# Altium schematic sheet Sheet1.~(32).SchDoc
size A; SheetNumber: 1; SheetTotal: 1
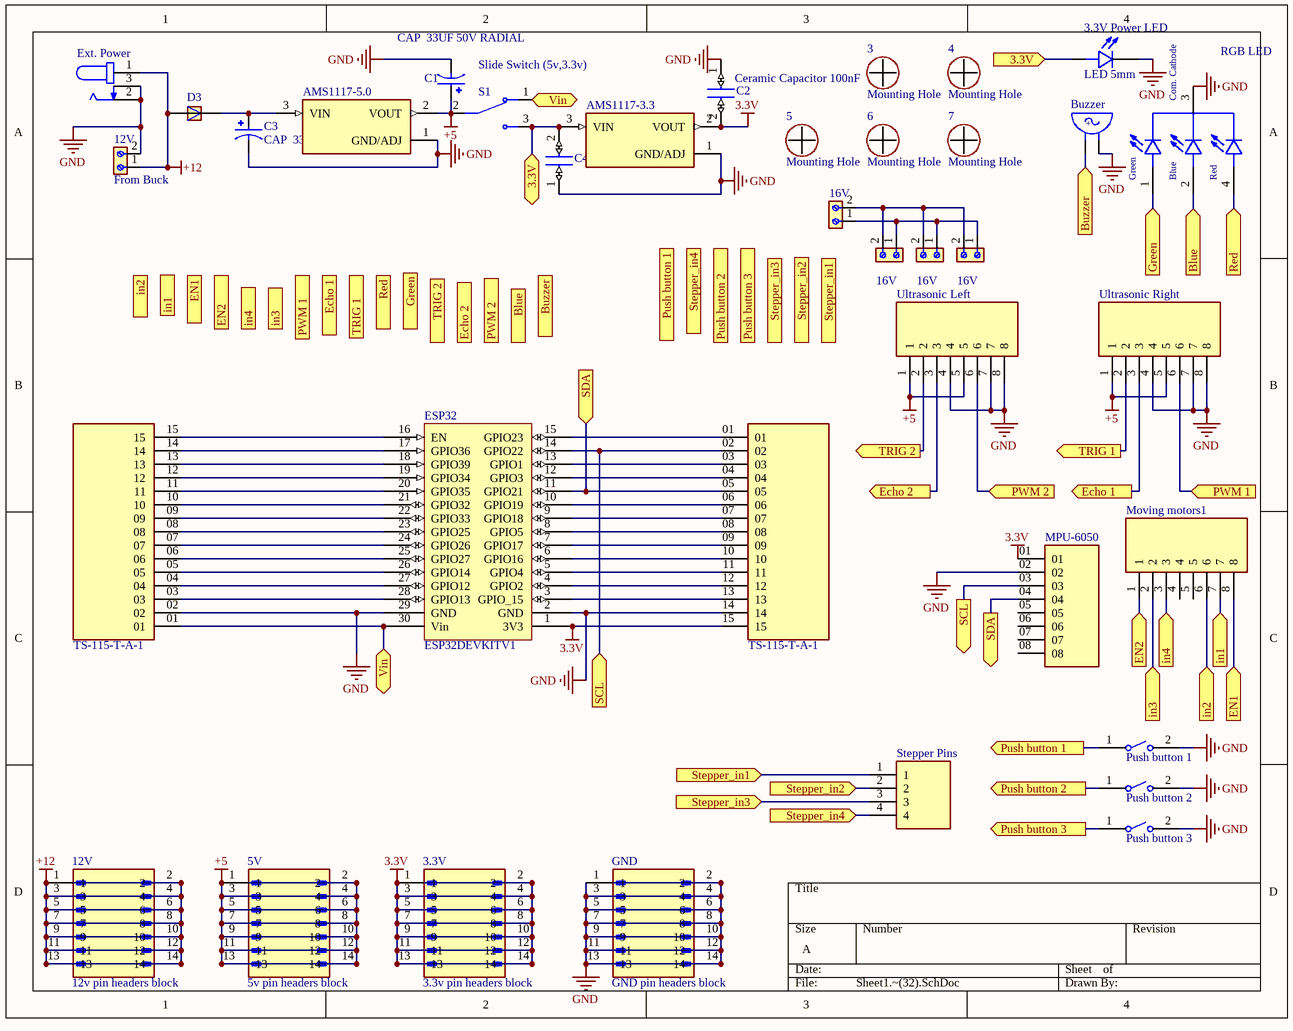
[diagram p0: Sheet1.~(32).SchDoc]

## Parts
(Parts that share a designator on the sheet are numbered #1, #2 ... from top to bottom, then left to right.)
3  Mounting Hole  [PCBComponent_1]
3.3V  3.3v pin headers block  [AMPHENOL_52601-S14-4LF]
3.3V_Power_LED  LED 5mm  [LED 5mm]
4  Mounting Hole  [PCBComponent_1]
5  Mounting Hole  [PCBComponent_1]
5V  5v pin headers block  [AMPHENOL_52601-S14-4LF]
6  Mounting Hole  [PCBComponent_1]
7  Mounting Hole  [PCBComponent_1]
12V#1  From Buck  [691213510002]
12V#2  12v pin headers block  [AMPHENOL_52601-S14-4LF]
16V#1  From Buck  [691213510002]  (value not drawn)
16V#2  From Buck  [691213510002]  (value not drawn)
16V#3  From Buck  [691213510002]  (value not drawn)
16V#4  From Buck  [691213510002]  (value not drawn)
AMS1117-3.3  AMS1117-3.3  [SOT229P700X180-4N]  (value not drawn)
AMS1117-5.0  AMS1117-5.0  [SOT229P700X180-4N]  (value not drawn)
Buzzer  Buzzer  [Buzzer 5V]  (value not drawn)
C1  CAP  33UF 50V RADIAL  [CAP  33UF 50V RADIAL]
C2  Ceramic Capacitor 100nF  [C320C]
C3  CAP  33UF 50V RADIAL  [CAP  33UF 50V RADIAL]
C4  Ceramic Capacitor 100nF  [C320C]  (value not drawn)
D3  RL207  [DIOAD1300W80L670D310]  (value not drawn)
ESP32  ESP32DEVKITV1  [ESP32DEVKITV1]
Ext._Power  DC Power Jack Female Socket  [DC Power Jack Female Socket]  (value not drawn)
GND  GND pin headers block  [AMPHENOL_52601-S14-4LF]
J5  TS-115-T-A-1  [SAMTEC_TS-115-T-A-1]
J6  TS-115-T-A-1  [SAMTEC_TS-115-T-A-1]
Moving_motors1  Pin header female block 8 pin  [Pin header female block 8 pin]  (value not drawn)
MPU-6050  MPU-6050  [MPU-6050]  (value not drawn)
Push_button_1  FSM8JRT  [TE_FSM8JRT]  (value not drawn)
Push_button_2  FSM8JRT  [TE_FSM8JRT]  (value not drawn)
Push_button_3  FSM8JRT  [TE_FSM8JRT]  (value not drawn)
RGB_LED  common cathode  [LED RGB 5mm]  (value not drawn)
S1  Slide Switch (5v,3.3v)  [Slide switch]
Stepper_Pins  Pin hreader 4 pins  [Pin hreader 4 pins]  (value not drawn)
Ultrasonic_Left  Pin header female block 8 pin  [Pin header female block 8 pin]  (value not drawn)
Ultrasonic_Right  Pin header female block 8 pin  [Pin header female block 8 pin]  (value not drawn)

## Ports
3.3V (bidir, see Sheet1[4A]), 3.3V (in, see Sheet1[2A]), Blue (in, see Sheet1[2B]), Blue (out, see Sheet1[4B]), Buzzer (in, see Sheet1[2B]), Buzzer (out, see Sheet1[4A]), Echo 1 (in, see Sheet1[4B]), Echo 1 (out, see Sheet1[2B]), Echo 2 (in, see Sheet1[3B]), Echo 2 (out, see Sheet1[2B]), EN1 (in, see Sheet1[1B]), EN1 (out, see Sheet1[4C]), EN2 (in, see Sheet1[1B]), EN2 (out, see Sheet1[4C]), Green (in, see Sheet1[2B]), Green (out, see Sheet1[4B]), in1 (in, see Sheet1[1B]), in1 (out, see Sheet1[4C]), in2 (in, see Sheet1[1B]), in2 (out, see Sheet1[4C]), in3 (in, see Sheet1[1B]), in3 (out, see Sheet1[4C]), in4 (in, see Sheet1[1B]), in4 (out, see Sheet1[4C]), Push button 1 (in, see Sheet1[4C]), Push button 1 (out, see Sheet1[3B]), Push button 2 (in, see Sheet1[4D]), Push button 2 (out, see Sheet1[3B]), Push button 3 (in, see Sheet1[4D]), Push button 3 (out, see Sheet1[3B]), PWM 1 (in, see Sheet1[1B]), PWM 1 (out, see Sheet1[4B]), PWM 2 (in, see Sheet1[2B]), PWM 2 (out, see Sheet1[4B]), Red (in, see Sheet1[2B]), Red (out, see Sheet1[4B]), SCL (in, see Sheet1[3C]), SCL (out, see Sheet1[2C]), SDA (in, see Sheet1[4C]), SDA (out, see Sheet1[2B]), Stepper_in1 (in, see Sheet1[3B]), Stepper_in1 (in, see Sheet1[3D]), Stepper_in2 (in, see Sheet1[3B]), Stepper_in2 (in, see Sheet1[3D]), Stepper_in3 (in, see Sheet1[3B]), Stepper_in3 (in, see Sheet1[3D]), Stepper_in4 (in, see Sheet1[3B]), Stepper_in4 (out, see Sheet1[3D]), TRIG 1 (in, see Sheet1[4B]), TRIG 1 (out, see Sheet1[2B]), TRIG 2 (out, see Sheet1[2B]), TRIG 2 (out, see Sheet1[3B]), Vin (bidir, see Sheet1[2A]), Vin (bidir, see Sheet1[2C])

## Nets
3.3V: 3.3V.1 3.3V.2 3.3V.3 3.3V.4 3.3V.5 3.3V.6 3.3V.7 3.3V.8 3.3V.9 3.3V.10 3.3V.11 3.3V.12 3.3V.13 3.3V.14 AMS1117-3.3.2(VOUT) C2.2 ESP32.1(3V3) J5.15 MPU-6050.01
+5: 5V.1 5V.2 5V.3 5V.4 5V.5 5V.6 5V.7 5V.8 5V.9 5V.10 5V.11 5V.12 5V.13 5V.14 AMS1117-5.0.2(VOUT) C1.P S1.2 Ultrasonic_Left.1 Ultrasonic_Left.5 Ultrasonic_Right.1 Ultrasonic_Right.5
+12: 12V#1.1 12V#2.1 12V#2.2 12V#2.3 12V#2.4 12V#2.5 12V#2.6 12V#2.7 12V#2.8 12V#2.9 12V#2.10 12V#2.11 12V#2.12 12V#2.13 12V#2.14 D3.A Ext._Power.1
GND: 3.3V_Power_LED.C 12V#1.2 AMS1117-3.3.1(GND/ADJ) AMS1117-5.0.1(GND/ADJ) Buzzer.NEG C1.N C2.1 C3.N C4.1 ESP32.2(GND) ESP32.29(GND) Ext._Power.2 Ext._Power.3 GND.1 GND.2 GND.3 GND.4 GND.5 GND.6 GND.7 GND.8 GND.9 GND.10 GND.11 GND.12 GND.13 GND.14 J5.14 J6.02 MPU-6050.02 Push_button_1.2 Push_button_2.2 Push_button_3.2 RGB_LED.3(Com._Cathode) Ultrasonic_Left.4 Ultrasonic_Left.7 Ultrasonic_Left.8 Ultrasonic_Right.4 Ultrasonic_Right.7 Ultrasonic_Right.8
3.3V: 3.3V_Power_LED.A AMS1117-3.3.3(VIN) C4.2 S1.3 ; port 3.3V  [a separate net that carries the same name]
Blue: RGB_LED.2(BLUE) ; port Blue
Buzzer: Buzzer.POS ; port Buzzer
Echo 1: Ultrasonic_Right.3 ; port Echo 1
Echo 2: Ultrasonic_Left.3 ; port Echo 2
EN1: Moving_motors1.8 ; port EN1
EN2: Moving_motors1.1 ; port EN2
Green: RGB_LED.1(Green) ; port Green
in1: Moving_motors1.7 ; port in1
in2: Moving_motors1.6 ; port in2
in3: Moving_motors1.2 ; port in3
in4: Moving_motors1.3 ; port in4
Push button 1: Push_button_1.1 ; port Push button 1
Push button 2: Push_button_2.1 ; port Push button 2
Push button 3: Push_button_3.1 ; port Push button 3
PWM 1: Ultrasonic_Right.6 ; port PWM 1
PWM 2: Ultrasonic_Left.6 ; port PWM 2
Red: RGB_LED.4(Red) ; port Red
SCL: ESP32.14(GPIO22) J5.02 MPU-6050.03 ; port SCL
SDA: ESP32.11(GPIO21) J5.05 MPU-6050.04 ; port SDA
Stepper_in1: Stepper_Pins.1 ; port Stepper_in1
Stepper_in2: Stepper_Pins.2 ; port Stepper_in2
Stepper_in3: Stepper_Pins.3 ; port Stepper_in3
Stepper_in4: Stepper_Pins.4 ; port Stepper_in4
TRIG 1: Ultrasonic_Right.2 ; port TRIG 1
TRIG 2: Ultrasonic_Left.2 ; port TRIG 2
Vin: ESP32.30(Vin) J6.01 S1.1 ; port Vin
Net16V#1_1: 16V#1.1 16V#2.1 16V#3.1 16V#4.1
Net16V#1_2: 16V#1.2 16V#2.2 16V#3.2 16V#4.2
NetAMS1117-5.0_3: AMS1117-5.0.3(VIN) C3.P D3.C
NetESP32_3: ESP32.3(GPIO_15) J5.13
NetESP32_4: ESP32.4(GPIO2) J5.12
NetESP32_5: ESP32.5(GPIO4) J5.11
NetESP32_6: ESP32.6(GPIO16) J5.10
NetESP32_7: ESP32.7(GPIO17) J5.09
NetESP32_8: ESP32.8(GPIO5) J5.08
NetESP32_9: ESP32.9(GPIO18) J5.07
NetESP32_10: ESP32.10(GPIO19) J5.06
NetESP32_12: ESP32.12(GPIO3) J5.04
NetESP32_13: ESP32.13(GPIO1) J5.03
NetESP32_15: ESP32.15(GPIO23) J5.01
NetESP32_16: ESP32.16(EN) J6.15
NetESP32_17: ESP32.17(GPIO36) J6.14
NetESP32_18: ESP32.18(GPIO39) J6.13
NetESP32_19: ESP32.19(GPIO34) J6.12
NetESP32_20: ESP32.20(GPIO35) J6.11
NetESP32_21: ESP32.21(GPIO32) J6.10
NetESP32_22: ESP32.22(GPIO33) J6.09
NetESP32_23: ESP32.23(GPIO25) J6.08
NetESP32_24: ESP32.24(GPIO26) J6.07
NetESP32_25: ESP32.25(GPIO27) J6.06
NetESP32_26: ESP32.26(GPIO14) J6.05
NetESP32_27: ESP32.27(GPIO12) J6.04
NetESP32_28: ESP32.28(GPIO13) J6.03

Not connected (* = marked no-connect by the designer): Moving_motors1 4 5; MPU-6050 05 06 07 08

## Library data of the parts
3.3V 5V 12V#2 GND = 52601-S14-4LF: MF: {'manufacturer': u'Amphenol ICC (FCI)'}
3.3V_Power_LED = LED 5mm: Red 623nm LED Indication - Discrete 1.9V Radial; MF: {'manufacturer': u'Wurth Elektronik'}; MP: 151054RS03000
12V#1 16V#1-16V#4 = Terminal Block: 2 Position Wire to Board Terminal Block Horizontal with Board 0.200 (5.08mm) Through Hole; MF: Wurth Electronics
AMS1117-3.3 = AMS1117-3.3: MF: {'manufacturer': u'Advanced Monolithic Systems'}
AMS1117-5.0 = AMS1117-5.0: MF: {'manufacturer': u'Advanced Monolithic Systems'}
Buzzer = Buzzer 5V: BUZZER 2.3KHZ 4-6VDC; MF: {'manufacturer': u'Soberton Inc.'}; MP: WST-1205S
C1 C3 = CAP  33UF 50V RADIAL: NHG-A; MF: {'manufacturer': u'Panasonic'}; MP: ECA1HHG330I
C2 C4 = Ceramic Capacitor 100nF: 0.1ÂµF Â±20% 50V Ceramic Capacitor Z5U Radial; MF: KEMET; MP: C320C104M5U5TA
D3 = RL207: Semiconductors and Actives, Power Diodes, Discretes (diodes, transistors, thyristors ...), Diodes; MF: {'manufacturer': u'Diodes Inc.'}
Ext._Power = DC Power Jack Female Socket: 2.0 mm Center Pin, 2.5 A, Right Angle, Through Hole, Dc Power Jack Connector; MF: {'manufacturer': u'CUI Devices'}; MP: PJ-002A
J5 J6 = TS-115-T-A-1: MF: {'manufacturer': u'Samtec'}
Moving_motors1 Ultrasonic_Left Ultrasonic_Right = Pin header female block 8 pin: MF: {'manufacturer': u'TE Connectivity'}; MP: 5-534998-4
Push_button_1-Push_button_3 = FSM8JRT: Tactile Switches PUSHBUTTON SWITCH TACT; MF: {'manufacturer': u'TE Connectivity'}
RGB_LED = LED RGB 5mm: MF: {'manufacturer': u'Kingbright'}; MP: WP154A4SUREQBFZGC
S1 = Slide switch: MF: {'manufacturer': u'E-Switch'}; MP: EG1206
Stepper_Pins = Pin hreader 4 pins: MF: {'manufacturer': u'TE Connectivity'}; MP: 2355181-4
